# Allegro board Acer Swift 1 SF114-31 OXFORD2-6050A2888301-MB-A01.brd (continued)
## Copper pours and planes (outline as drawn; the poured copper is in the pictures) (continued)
P3V3AL on BOTTOM: 78.74,126.45 78.74,123.55 77.97,122.78 71.52,122.78 71.4,122.91 71.4,127.02 71.6,127.23 76.76,127.23 77.39,126.59 78.59,126.59
P3V3AL on BOTTOM: 65.5,126.82 65.5,128.22 64.13,128.22 64.13,126.82 64.03,126.72 63.32,126.72 62.51,127.53 62.51,128.57 63.32,129.39 68.81,129.39 69.36,128.83 73.78,128.83 75.69,126.92 75.13,126.36 72.03,126.36 71.02,127.38 67.18,127.38 66.52,126.72 65.61,126.72
P3V3S on TOP: 58.82,129.16 62.2,129.16 62.2,126.47 63.78,124.89 70.08,124.89 70.41,124.56 70.41,123.09 70.18,122.86 62.1,122.86 58.29,126.67 58.29,128.63
P3V3S on BOTTOM: 15.11,53.82 15.95,53.82 16.15,53.62 16.15,50.55 15.9,50.29 15.16,50.29 15.03,50.42 15.03,53.75
P3V3S on BOTTOM: 19.91,21.31 20.75,22.15 20.75,23.34 20.62,23.47 18.08,23.47 17.95,23.34 17.95,22.32 18.97,21.31
P3V3S on BOTTOM: 67.87,122.91 67.99,122.78 70.41,122.78 70.96,123.34 70.96,126.49 70.38,127.08 68.4,127.08 68.3,126.97 68.3,125.88 67.87,125.45
P3V3S on BOTTOM: 56.44,127.99 56.31,128.12 56.31,131.55 52.63,135.23 52.63,143.61 53.13,144.12 56.79,144.12 57.19,143.72 57.19,142.58 56.82,142.21 54.53,142.21 54.4,142.09 54.4,138.28 55.55,137.13 58.21,137.13 58.34,137.01 58.34,133.2 59.74,131.8 59.74,129.67 59.99,129.41 59.99,128.24 59.74,127.99
P3V3S on L4: 60.3,128.9 55.47,128.9 54.12,127.56 54.12,126.44 54.71,125.86 59.48,125.86 60.53,126.9 60.53,128.68
P3V3S on L5: 64.49,133.2 88.19,133.2 88.41,132.97 88.92,132.97 89.15,133.2 109.57,133.2 109.95,132.82 110.36,132.82 110.74,133.2 120.44,133.2 120.44,105.28 111.76,105.28 111.5,105.54 110.77,105.54 110.51,105.28 76.35,105.28 76.35,110.95 73.2,114.1 73.2,118.44 65.02,126.62 58.16,126.62 58.16,126.93 58.47,127.24 58.47,127.69 58.16,128 58.16,133.15 58.39,133.37 64.31,133.37
P3V3S_CR on TOP: 21,17.86 21,20.93 21.26,21.18 23.06,21.18 27.76,16.48 31.29,16.48 31.42,16.36 31.42,14.33 30.71,13.61 25.24,13.61
P3V3S_CR on BOTTOM: 20.11,18.87 20.11,21.1 20.7,21.69 24.94,21.69 25.07,21.56 25.07,20.42 24.81,20.17 22.4,20.17 22.27,20.04 20.57,20.04 20.42,19.88 20.42,18.89 20.39,18.87
P3V3S_LVDS1 on BOTTOM: 57.97,142.72 60.5,142.72 60.65,142.57 60.65,141.99 60.09,141.43 60.09,140.54 59.99,140.44 57.96,140.44 57.84,140.55 57.84,142.59
P3V3S_LVDS2 on BOTTOM: 60.75,139.17 60.63,139.29 60.63,140.23 60.37,140.49 60.37,141.17 60.91,141.71 60.91,142.62 61.01,142.72 61.77,142.72 61.9,142.85 61.9,143.81 65.66,147.57 65.66,150.01 66.24,150.6 66.24,152.27 67.36,153.39 68.02,153.39 68.15,153.26 68.15,151.1 67.28,150.24 67.28,147.75 63.34,143.81 63.34,140.72 61.79,139.17
P5V0A on TOP (solid shape): 36.12,123.88 36.12,121.97 32.81,118.67 32.05,118.67 31.85,118.87 31.85,121.06 34.92,124.13 35.86,124.13
P5V0A on TOP (solid shape): 38.48,139.34 38.48,138.61 38.05,138.18 37,138.18 35.61,136.78 34.59,136.78 34.59,137.92 36.42,139.75 38.07,139.75
P5V0A on L3 (solid shape): 39.04,139.17 39.04,138.25 38.68,137.9 36.85,137.9 36.17,138.58 36.17,139.29 36.62,139.75 38.45,139.75
P5V0A on L3 (solid shape): 73.3,136.96 73.3,133.43 84.86,121.87 85.65,121.87 85.95,121.56 85.95,121.21 84.99,120.24 84.15,120.24 71.73,132.66 71.73,136.32 69.95,138.1 68.53,138.1 68.53,139.62 70.63,139.62
P5V0A on TOP: 96.77,126.42 93.11,126.42 91.89,125.2 88.34,125.2 84.43,121.28 84.43,120.5 84.68,120.24 86.1,120.24 89.07,123.21 96.14,123.21 97.08,124.15 97.08,126.11
P5V0A on BOTTOM: 105.2,101.96 105.2,107.87 105.53,108.2 107.67,108.2 108.35,107.52 108.35,101.68 107.87,101.19 107.11,101.19 106.47,101.83 105.33,101.83
P5V0A on BOTTOM: 32.66,117.98 33.6,118.92 33.6,120.29 32.61,121.28 24.69,121.28 23.26,119.86 21.38,119.86 21,119.48 21,118.19 21.21,117.98
P5V0A on BOTTOM: 94.99,109.12 94.99,110.41 95.55,110.97 95.55,112.22 95.42,112.34 94.03,112.34 93.65,111.96 93.65,109.17 93.77,109.04 94.92,109.04
P5V0A on BOTTOM: 104.09,144.83 104.09,144.02 103.93,143.87 101.55,143.87 101.34,144.07 101.34,144.91 101.47,145.03 103.88,145.03
P5V0A on BOTTOM: 96.59,123.67 95.2,123.67 94.66,124.21 92.01,124.21 91.94,124.18 91.26,124.87 91.26,125.7 91.34,125.78 92.43,125.78 92.58,125.93 92.58,126.52 92.91,126.85 93.65,126.85 94.15,127.36 94.79,127.36 95.3,126.85 96.69,126.85 97.08,126.47 97.08,124.15
P5V0A on L4: 102.69,122.15 98.35,122.15 97.08,123.42 97.08,126.47 96.95,126.59 93.01,126.59 92.5,126.09 92.5,110.51 96.62,106.4 105.8,106.4 106.06,106.66 106.06,118.78
P5V0A_USB1 on BOTTOM: 20.39,116.74 18.89,116.74 18.67,116.51 16.86,116.51 16.51,116.15 15.87,116.15 15.26,116.76 15.26,118.19 16.1,119.02 20.65,119.02 20.8,118.87 20.8,117.86 20.93,117.73 22.32,117.73 22.45,117.6 22.45,115.19 22.32,115.06 20.93,115.06 20.8,115.19 20.8,116.33
P5V0A_USB2 on BOTTOM: 103.45,84.07 103.45,89.94 101.06,92.33 101.06,94.87 101.19,95 107.06,95 110.18,98.12 113.46,98.12 113.61,98.27 113.61,100.28 113.59,100.28 113.46,100.41 112.04,100.41 111.88,100.56 111.88,101.14 112.19,101.45 112.8,101.45 113.05,101.7 114.78,101.7 115.08,101.4 115.08,100.35 115.49,99.95 115.49,96.85 115.01,96.37 110.89,96.37 108.91,94.39 108.91,87.81 106.17,87.81 106.02,87.65 106.02,84.4 105.69,84.07
P5V0A_USB2_DB on TOP: 31.83,151.94 31.98,151.79 31.98,151.34 30.96,150.31 30.96,149.46 30.88,149.39 29.83,149.39 29.23,149.99 27.24,149.99 27.17,150.06 27.17,151.23 27.65,151.71 28.05,151.71 28.15,151.81 28.15,153.03 28.2,153.08 28.81,153.08 28.87,153.02 28.87,152.04 28.86,152.02 28.89,152.02 29.18,151.73 30.44,151.73 30.66,151.94
P5V0A_USB2_DB on BOTTOM: 48.9,160.09 48.9,157.87 48.78,157.75 47.45,157.75 47.21,157.98 47.21,159.96 47.34,160.09
P5V0A_USB2_DB on L3, L4: 18.06,148.65 17.46,149.25 17.46,152.2 17.58,152.32 21.15,152.32 21.29,152.3 21.42,152.23 22.04,152.16 22.46,152.63 23.91,152.63 23.91,152.62 38.84,152.62 45.33,159.11 49.15,159.11 49.51,158.75 49.51,155.07 43.78,149.34 22.59,149.34 21.9,148.65
P5V0A_USB_PW1 on BOTTOM: 105.53,98.83 105.53,100.89 108.1,100.89 108.56,101.35 110.74,101.35 111.02,101.07 111.02,100.1 110.54,99.62 109.22,99.62 108.2,98.6 105.76,98.6
P5V0S on BOTTOM: 19.35,50.14 16,50.14 15.85,49.99 15.85,49.33 16.81,48.36 19.35,48.36 19.48,48.49 19.48,50.01
P5V0S on BOTTOM: 87.5,122.2 87.5,123.6 88.11,124.21 88.11,124.99 87.91,125.2 84.76,125.2 84.17,125.78 83.16,125.78 82.57,125.2 82.57,122.15 87.45,122.15
P5V0S on BOTTOM: 8.1,58.04 8.1,59.56 14.2,59.56 14.32,59.44 14.32,58.93 13.43,58.04
P5V0S on L4: 39.21,132.33 66.11,132.33 71.04,127.41 84.19,127.41 84.86,126.74 84.86,124.26 83.84,123.24 70.71,123.24 64.79,129.16 45.69,129.16 20.39,103.86 20.39,57.66 20.37,57.63 17.52,57.63 16.94,57.05 15.97,57.05 15.39,57.63 12.37,57.63 12.24,57.76 12.24,59.79 12.37,59.92 17.45,59.92 18.12,60.59 18.12,109.49 37.92,129.29 37.92,131.04
P5V0S_AUDIO_AVDD on BOTTOM: 12.37,57.78 13.43,56.72 13.43,55.88 13.18,55.63 7.21,55.63 7.08,55.75 7.08,57.78
P5V0S_PVDD on BOTTOM: 14.78,50.11 12.06,50.11 11.68,49.73 11.1,49.73 10.41,49.05 10.41,48.44 10.87,47.98 11.4,47.98 11.88,48.46 14.45,48.46 14.96,48.97 14.96,49.94
PVBAT on TOP: 75.97,11.58 66.85,20.7 58.26,20.7 55.72,23.24 54.58,23.24 51.71,20.37 46.91,20.37 45.56,21.72 45.56,30.38 46.81,31.62 71.8,31.62 73.58,33.4 84.96,33.4 89.56,28.8 104.37,28.8 106.88,31.32 106.88,38.43 105.33,39.98 105.33,40.41 104.97,40.77 104.97,42.58 104.06,43.48 104.06,45.54 103.53,46.08 103.53,49.83 104.97,51.27 104.97,97.57 107.73,100.33 107.73,116.93 102.92,121.74 99.82,121.74 98.24,123.32 98.24,125.65 96.28,127.62 95.04,127.62 92.94,129.72 88.67,129.72 87.09,128.14 82.42,128.14 81.99,127.71 81.73,127.71 81.3,128.14 75.23,128.14 68.22,135.15 67.76,135.15 67.43,135.48 67.43,137.44 67.64,137.64 72.49,137.64 76.78,133.35 82.9,133.35 84.78,135.23 96.08,135.23 99.88,131.43 107.86,131.43 115.49,123.8 115.49,90.73 124.69,90.73 124.69,16.53 109.62,16.53 109.62,12.01 109.19,11.58
PVBAT on BOTTOM: 102.1,78.21 102.1,79.25 102.38,79.53 105.53,79.53 105.89,79.17 105.89,76.86 105.64,76.61 101.7,76.61 101.52,76.78 101.52,77.62
PVBAT on BOTTOM: 83.82,131.42 83.23,132 83.23,133.55 84.27,134.59 84.27,138.53 84.1,138.71 84.1,141.83 84.27,142.01 84.27,145.72 83.84,146.15 83.33,146.15 82.83,146.66 82.83,148.21 82.09,148.95 82.09,150.44 81.38,151.15 81.38,153.24 81.56,153.42 82.22,153.42 82.5,153.14 82.5,151.99 83.84,150.65 83.84,147.73 85.8,145.77 87.04,145.77 87.27,145.54 87.27,144.47 86.61,143.81 86.61,131.65 86.38,131.42
PVBAT on BOTTOM: 85.32,32.38 85.11,32.59 78.89,32.59 78.36,33.12 78.36,36.88 79.14,37.67 90.73,37.67 91.13,37.26 91.13,32.82 90.7,32.38
PVBAT on BOTTOM: 52.12,21.89 52.12,19.48 51.43,18.8 47.65,18.8 47.42,19.02 47.42,19.76 48.01,20.35 48.01,21.77 48.41,22.17 51.84,22.17
PVBAT on BOTTOM: 72.29,26.42 75.41,26.42 75.79,26.03 75.79,25.09 75.41,24.71 72.29,24.71 72.11,24.89 72.11,26.24
PVBAT on BOTTOM: 70.02,135.76 70.02,143.23 66.49,143.23 66.29,143.02 66.29,135.25 69.52,135.25
PVBAT_CPU on BOTTOM: 94.21,81.03 102.18,81.03 102.41,80.8 102.41,80.06 101.8,79.45 101.8,78.76 101.11,78.08 101.11,76.96 100.89,76.73 99.54,76.73 98.27,78 94.48,78 94.05,78.43 94.05,80.87
PVBAT_VGG on BOTTOM: 84.91,43.36 89.23,43.36 89.56,43.69 93.06,43.69 93.27,43.48 93.27,39.34 92.53,38.61 87.7,38.61 85.7,40.61 84.93,40.61 84.53,41.02 84.53,42.98
PVADPTR on TOP: 19.61,114.63 19.61,105.71 19.91,105.41 21.41,105.41 22.45,106.45 22.45,111.12 31.21,119.89 31.21,133.63 30.68,134.16 26.95,134.16 26.59,133.81 26.59,121.61
PVADPTR on TOP: 32.1,15.72 32.1,19.61 32.33,19.84 53.29,19.84 54.1,19.02 54.1,15.62 53.92,15.44 32.38,15.44
PVADPTR on BOTTOM: 20.24,41.5 20.24,55.9 18.74,57.4 18.74,66.62 16.86,68.5 16.86,106.07 17.9,107.11 21.28,107.11 21.51,106.88 21.51,105.56 19.35,103.4 19.35,70.66 21.46,68.55 21.46,58.34 23.01,56.79 23.01,38.02 14.22,29.23 14.22,13.84 17.24,10.82 21.38,10.82 27.85,17.29 27.85,19.21 29.06,20.42 34.08,20.42 34.95,19.56 34.95,18.31 34.69,18.06 32.56,18.06 32.33,17.83 32.33,13.74 31.01,12.41 31.01,5.98 10.06,5.98 10.06,31.32
PVADPTR on BOTTOM: 28.04,134.21 24.91,134.21 24.43,133.73 24.43,132.46 26.34,130.56 28.14,130.56 28.32,130.73 28.32,133.93
PVCORE on BOTTOM (solid shape): 99.23,101.4 99.23,98.55 98.98,98.3 94.15,98.3 93.24,97.38 93.24,85.65 92.76,85.17 90.19,85.17 90.09,85.27 90.09,85.85 91.28,85.85 91.28,86.38 90.09,86.38 90.09,86.6 88.3,88.39 88.3,94.42 86.03,96.7 86.03,99.26 85.09,100.2 85.09,101.55 85.21,101.68 98.96,101.68
PVCORE on TOP: 65.73,82.7 65.86,82.57 65.86,82.19 65.73,82.06 65.48,82.06 65.35,81.94 65.35,80.64 62.96,80.64 62.96,81.84 63.04,81.91 63.43,81.91 63.43,81.47 63.62,81.28 64.26,81.28 64.45,81.47 64.45,81.91 64.51,81.91 65.3,82.7
PVCORE on TOP: 62.94,84.73 63.7,85.49 63.7,86.38 63.83,86.51 64.22,86.51 64.22,85.72 64.27,85.67 64.27,85.21 64.3,85.19 64.3,84.3 64.45,84.15 64.45,83.7 64.33,83.59 63.06,83.59 62.94,83.72
PVCORE on BOTTOM: 63.15,80.67 64.97,80.67 65.1,80.79 65.1,81.56 65.86,82.32 65.86,82.57 65.48,82.95 65.13,82.95 64.9,82.72 64.73,82.72 64.5,82.95 63.45,82.95 63.45,82.19 63,81.75 63,81.56 63.15,81.4 63.15,81.12 63,80.97 63,80.82
PVCORE on BOTTOM: 63.19,83.72 64.21,83.72 64.59,84.1 64.59,84.86 65.35,85.62 65.35,86 64.59,86.76 63.57,86.76 63.45,86.64 63.45,85.24 63.06,84.86 63.06,83.84
PVCORE on L4: 78.79,82.04 69.21,82.04 68.91,81.74 68.91,80.54 68.63,80.26 67.26,80.26 66.95,79.96 63.8,79.96 63.07,80.7 63.07,82.04 63.65,82.63 63.65,83.41 63.17,83.9 63.17,85.84 63.94,86.61 64.81,87.48 64.81,89.43 65.35,89.97 69.16,89.97 69.16,87.68 70.23,86.61 71.73,86.61 73.89,88.77 73.89,93.62 74.29,94.03 74.29,99.19 77.69,102.59 88.9,102.59 91.23,100.25 91.23,89.99 89.05,87.81 84.55,87.81
PVCORE on L5: 65.81,80.73 65.34,80.26 60.49,80.26 60.49,84.51 61.76,85.78 61.76,87.29 62.51,88.04 62.51,92.13 64.03,93.65 64.03,93.68 64.01,93.7 64.01,94.37 64.13,94.5 64.13,98.25 65.81,99.92 65.81,102.41 68.42,105.03 91.23,105.03 91.23,96.04 91.08,95.88 73.1,95.88 67.54,90.32 67.54,89.18 67.11,88.76 67.11,84.43 65.1,84.43 65.1,83.21 65.81,82.5
PVGG on TOP: 63.67,76.33 64.11,75.89 65.27,75.89 65.55,76.17 65.55,78.43 65.07,78.92 64.69,78.92 64.52,78.74 64.52,78.38 64.31,78.17 63.8,78.17 63.67,78.05
PVGG on BOTTOM: 83,51.49 84.2,50.29 90.75,50.29 91.44,50.98 91.44,52.58 89.53,54.48 89.53,55.68 89.25,55.96 84.35,55.96 83,54.61
PVGG on BOTTOM: 63.86,76.83 63.86,76.19 64.33,75.71 65.99,75.71 66.24,75.97 66.24,77.49 65.31,78.42 65.31,79.05 64.46,79.91 62.81,79.91 62.68,79.78 62.68,79.65 63.57,78.76 63.57,78.51 63.45,78.38 63.45,77.25
PVGG on BOTTOM: 90.04,64.11 87.68,64.11 87.6,64.03 87.6,63.19 87.63,63.17 90.04,63.17 90.09,63.22 90.09,64.06
PVGG on L4: 64.41,78.87 65.88,78.87 66.24,78.51 66.24,76.45 70.08,72.62 70.08,69.6 70.38,69.29 73.58,69.29 74.34,68.53 84.05,68.53 84.76,67.82 84.76,62.97 85.29,62.43 87.09,62.43 87.53,62.86 87.53,64.11 87.78,64.36 90.27,64.36 90.9,63.73 90.9,53.62 89.3,52.02 74.19,52.02 64.77,61.44 64.77,62.56 64.11,63.22 64.11,68.25 63.95,68.4 63.95,69.42 63.24,70.13 62.84,70.13 62.84,77.29 ; 1 cut-out
PVGG on L5: 68.02,74.68 69.52,73.18 69.52,70 70.23,69.29 73.58,69.29 74.34,68.53 84.05,68.53 84.76,67.82 84.76,62.97 85.29,62.43 89.96,62.43 89.96,52.68 87.22,49.94 84.76,49.94 83.13,48.31 70.46,48.31 69.14,49.63 69.14,57.07 64.77,61.44 64.77,62.56 64.11,63.22 64.11,68.25 63.95,68.4 63.95,69.42 63.24,70.13 62.51,70.13 62.07,70.56 62.07,76.48 61.72,76.83 61.72,78.94 62.78,80.01 65.73,80.01 68.02,77.72 ; 1 cut-out
PVPACK on BOTTOM: 82.7,29.69 86.48,29.69 86.76,29.97 86.76,31.98 86.89,32.11 89.48,32.11 89.89,31.7 89.89,28.96 88.21,27.28 88.21,23.52 87.96,23.27 85.19,23.27 84.73,23.72 84.73,26.69 84.45,26.97 82.62,26.97 82.47,27.13 82.47,29.46
SDIO_V3P3A_V1P8A on BOTTOM: 75.43,69.29 76.53,69.29 78.89,66.93 78.89,64.06 78.64,63.8 77.44,63.8 77.34,63.91 77.34,66.22 75.38,68.17 75.38,69.24
UNNAMED_5_BEADSINGLE_I57_INA on BOTTOM: 74.95,30.45 75.03,30.38 75.03,29.97 74.9,29.84 74.24,29.84 74.14,29.74 74.14,27.63 73.91,27.41 70.58,27.41 68.63,29.36 68.63,30.17 68.91,30.45
UNNAMED_5_BEADSINGLE_I76_INA on BOTTOM: 23.97,134.87 23.97,139.01 24.36,139.39 27.2,139.39 27.73,138.86 27.73,134.95 27.38,134.59 24.25,134.59
UNNAMED_5_POWERINDUCTOR_I49_2 on BOTTOM: 84.25,25.45 81.76,25.45 80.92,26.29 77.11,26.29 76.6,25.78 76.6,23.85 76.17,23.42 76.17,23.01 76.43,22.76 80.64,22.76 81.45,23.57 84.2,23.57 84.43,23.8 84.43,25.27
UNNAMED_6_CSC0805_I6_A on BOTTOM: 92.88,145.52 92.76,145.64 87.75,145.64 87.63,145.52 87.63,144.14 87.04,143.56 87.04,142.72 87.17,142.6 90.09,142.6 90.22,142.47 90.22,141.71 90.34,141.58 91.61,141.58 92.5,140.69 92.76,140.69 92.88,140.82
UNNAMED_6_CSC0805_I27_A on BOTTOM: 73.58,145.26 73.45,145.39 67.23,145.39 66.98,145.14 66.98,144.42 67.13,144.27 68.22,144.27 68.86,143.64 71.14,143.64 71.8,142.98 71.8,142.21 73.33,140.69 73.45,140.69 73.58,140.82
UNNAMED_9_IDUT4PIN_I34_2 on BOTTOM: 88.49,87.2 87.22,87.2 84.27,84.25 84.27,79.73 85.04,78.97 87.91,78.97 88.67,79.73 88.67,87.02
UNNAMED_11_IDUT4PIN_I27_2 on BOTTOM: 81.28,53.77 79.68,53.77 79.37,53.47 79.37,51.56 78.64,50.82 78.64,48.16 79.09,47.7 82.95,47.7 83.36,48.11 83.36,50.22 82.39,51.18 82.39,51.59 82.09,51.89 81.68,51.89 81.63,51.94 81.63,53.42
UNNAMED_13_CSC0603_I58_A on BOTTOM: 97.51,123.37 97.46,123.42 94.79,123.42 94.28,123.93 93.39,123.93 93.27,123.8 93.27,122.78 93.39,122.66 95.55,122.66 95.68,122.53 95.68,118.72 97.46,116.94 97.96,116.94 97.96,117.96 97.51,118.41
UNNAMED_13_CSC0603_I80_A on BOTTOM: 95.88,110.54 95.35,110.01 95.35,108.94 95.6,108.69 97.69,108.69 97.84,108.84 97.84,114.02 97.33,114.02 95.88,112.57
UNNAMED_15_APL3523A_I201_8 on BOTTOM: 90.04,125.65 90.04,122.22 89.96,122.15 88.06,122.15 87.83,122.38 87.83,123.19 88.41,123.77 88.41,125.07 89.13,125.78 89.91,125.78
UNNAMED_15_APL3523A_I201_13 on BOTTOM: 90.04,127.28 90.04,128.68 89.3,129.41 88.87,129.41 88.72,129.26 88.72,128.75 88.19,128.22 88.19,127.61 88.31,127.48 88.69,127.48 89,127.18 89.94,127.18
UNNAMED_15_APL3523A_I202_8 on BOTTOM: 66.42,126.26 66.42,125.75 66.16,125.5 65.61,125.5 65.5,125.4 65.5,124.48 65.81,124.18 65.81,123.82 65.99,123.65 66.24,123.65 66.77,124.18 67.23,124.18 67.43,124.38 67.43,125.75 68.02,126.34 68.02,126.97 67.92,127.08 67.23,127.08
UNNAMED_15_APL3523A_I202_13 on BOTTOM: 62.07,125.98 61.52,125.42 61.52,124.31 61.9,123.92 63.49,123.92 64.13,124.56 64.13,125.5 63.47,125.5 63.29,125.68 63.29,126.34 62.58,127.05 62.13,127.05 62.07,127
UNNAMED_24_CSC0402_I46_A on TOP: 99.72,37.39 102.38,37.39 103.02,36.75 103.02,34.57 102.61,34.16 100.81,34.16 100.17,33.53 98.68,33.53 97.2,35 97.2,42.42 97.58,42.8 98.93,42.8 99.44,42.29 99.44,37.67
UNNAMED_24_CSC0402_I46_A on BOTTOM: 100.81,36.37 102.69,36.37 103.07,35.99 103.07,33.98 102.59,33.5 100.78,33.5 100.33,33.96 100.33,35.89
UNNAMED_51_ALC233VB2CGT_I110_AV on BOTTOM (solid shape): 13.1,43.61 13.1,43.18 12.32,42.39 12.32,42.11 11.76,41.55 11.76,40.97 11.63,40.84 11.3,40.84 11.05,41.1 11.05,43.79 11.15,43.89 12.82,43.89
VRA3V3A_LDO on BOTTOM: 76.73,139.29 76.98,139.04 77.47,139.04 77.64,139.22 77.64,139.93 77.24,140.33 77.24,141.1 77.77,141.63 77.77,143.03 77.62,143.18 76.91,143.18 76.73,143
VRACHG_ACDRV1 on TOP: 53.31,20.57 53.31,20.19 54.43,19.07 54.43,18.34 54.53,18.24 55.47,18.24 55.8,18.57 55.8,20.17 55.27,20.7 53.44,20.7
VRACHG_CMSRC1 on TOP: 56.56,20.88 57.05,20.88 57.55,20.37 57.55,17.04 57.48,16.97 56.44,16.97 55.34,15.87 54.61,15.87 54.43,16.05 54.43,17.73 54.53,17.83 55.5,17.83 56.16,18.49 56.16,20.47
VRACHG_MP1 on TOP: 62.91,19.3 61.11,19.3 60.63,19.79 58.09,19.79 57.88,19.58 57.88,15.67 58.11,15.44 62.99,15.44 63.4,15.85 63.4,18.82
VRACHG_PH on BOTTOM (solid shape): 82.06,31.9 82.06,29.67 80.67,28.27 77.64,28.27 75.18,30.73 72.34,30.73 72.26,30.81 72.26,31.67 72.36,31.77 75.79,31.77 76.17,32.16 81.81,32.16
VRACHG_REGN on BOTTOM: 65.61,25.58 68.55,25.58 68.7,25.42 68.7,24.51 68.35,24.15 66.65,24.15 66.19,23.7 65.78,23.7 65.48,24 65.48,25.45
VRP1V05A on BOTTOM: 88.31,107.42 88.31,104.83 88.62,104.52 98.7,104.52 99.49,103.73 99.49,102.97 99.62,102.84 102.66,102.84 103.17,102.34 103.93,102.34 104.06,102.46 104.06,104.37 103.93,104.5 101.55,104.5 101.19,104.85 101.19,106.91 100.4,107.7 88.59,107.7
VRP1V05A_PH on BOTTOM (solid shape): 97.08,114.15 95.55,112.62 93.95,112.62 92.2,110.87 88.54,110.87 88.49,110.92 88.49,113.18 88.72,113.41 90.78,113.41 91.84,114.48 93.01,114.48 93.37,114.83 97.08,114.83
VRP1V5S on BOTTOM: 103.17,115.67 103.17,116.43 103.3,116.56 104.8,116.56 105.23,116.13 105.23,115.59 104.92,115.29 104.92,114.81 104.87,114.76 104.34,114.76 104.24,114.86 104.24,115.37 104.06,115.54 103.3,115.54
VRP1V8A on BOTTOM (solid shape): 105.47,117.96 105.47,117.8 105.34,117.67 104.94,117.67 104.31,117.04 102.03,117.04 101.24,116.26 100.1,116.26 100.02,116.33 100.02,116.89 99.74,117.17 99.74,117.73 100.23,118.21 105.22,118.21
VRP1V8A on TOP: 97.15,121.69 90.32,121.69 89.46,120.83 89.46,117.7 90.4,116.76 104.29,116.76 105.33,117.8 105.33,118.24 104.8,118.77 100.07,118.77
VRP1V8A on BOTTOM: 90.6,122.4 90.09,121.89 89.33,121.89 89.2,121.77 89.2,113.89 89.4,113.69 90.52,113.69 90.85,114.02 90.85,118.85 91.11,119.1 95.3,119.1 95.42,119.23 95.42,122.28 95.3,122.4
VRP1V8A_PH on BOTTOM (solid shape): 97.08,116.94 97.08,116.36 96.97,116.26 95.83,116.26 95.63,116.46 91.23,116.46 91.11,116.59 91.11,118.57 91.34,118.8 95.22,118.8
VRP1V15 on BOTTOM: 103.55,121.77 103.55,121.39 102.92,120.75 102.92,119.74 102.79,119.61 101.9,119.61 101.77,119.74 101.77,122.28 101.9,122.4 102.36,122.4 102.89,121.87 103.45,121.87
VRP1V24A on BOTTOM: 99.11,121.26 101.39,121.26 101.52,121.39 101.52,122.28 101.39,122.4 100,122.4 99.87,122.53 99.87,124.05 100,124.18 100.76,124.18 100.89,124.31 100.89,124.69 100.76,124.82 100.25,124.82 99.74,125.32 99.11,125.32 98.98,125.2 98.98,121.39
VRP3V3A on BOTTOM: 78.31,126.97 77.72,126.97 77.14,127.56 75.87,127.56 74.32,129.11 70.63,129.11 70.28,129.46 70.28,133.07 70.41,133.2 78.38,133.2 79.52,132.05 79.52,128.19
VRP3V3A_PH on BOTTOM: 73.2,140.31 73.2,139.04 73.07,138.91 72.06,138.91 71.93,138.79 71.93,138.02 71.8,137.9 70.41,137.9 70.28,137.77 70.28,135.36 70.41,135.23 74.6,135.23 75.41,136.04 75.41,138.28 74.72,138.96 74.72,140.31 74.6,140.44 73.33,140.44
VRP5V0A on BOTTOM: 89.84,132.46 89.84,129.92 90.4,129.36 93.67,129.36 93.9,129.13 93.9,127.74 94.03,127.61 95.04,127.61 95.55,127.1 96.44,127.1 98.35,129.01 100,129.01 100.29,129.3 100.29,132.74 99.86,133.17 90.55,133.17
VRP5V0A_PH on BOTTOM: 94.03,140.31 94.03,139.17 94.28,138.91 94.28,135.36 94.15,135.23 90.6,135.23 90.47,135.36 90.47,137.9 91.36,138.79 92.38,138.79 92.5,138.91 92.5,140.31 92.63,140.44 93.9,140.44
VRPCHG_LG on BOTTOM (solid shape): 75.89,32.89 75.89,32.31 75.66,32.08 74.47,32.08 74.42,32.13 74.42,32.89 74.57,33.04 75.74,33.04
VRPVCORE_PH1 on BOTTOM: 98.37,83.79 93.72,83.79 93.21,84.3 91.18,84.3 90.07,83.18 90.07,79.93 91.03,78.97 92.99,78.97 93.67,79.65 93.67,80.87 94.21,81.41 98.29,81.41 98.4,81.51 98.4,83.77
VRPVDDQ on BOTTOM: 38.94,35.58 39.82,35.58 40.18,35.23 41.55,35.23 41.91,35.58 50.49,35.58 51.58,34.49 51.58,31.77 50.62,30.81 46.89,30.81 45.39,32.31 38.5,32.31 38.33,32.49 38.33,34.98
VRPVDDQ_PH on BOTTOM (solid shape): 45.39,23.95 45.39,23.37 45.18,23.16 44.8,23.16 44.7,23.27 44.7,23.72 43.89,24.54 43.38,24.54 43.38,24.94 43.41,24.97 44.37,24.97
VRPVDDQ_PH on BOTTOM: 50.47,24.69 50.44,24.71 50.44,25.55 50.19,25.81 46.78,25.81 45.77,26.82 40.69,26.82 40.69,28.07 43.81,28.07 43.91,28.17 44.8,28.17 45.95,29.31 50.77,29.31 51.3,28.78 51.3,24.71 51.28,24.69
VRPVDDQ_VIN on BOTTOM: 43.58,26.47 43.68,26.57 45.62,26.57 47.09,25.09 47.09,19.02 46.83,18.77 45.46,18.77 45.01,19.23 45.01,20.62 45.74,21.36 45.74,24.28 44.73,25.3 42.08,25.3 41.96,25.42 41.96,26.36 42.06,26.47
VRPVGG_PH1 on BOTTOM: 89.2,46.02 79.5,46.02 78.91,45.44 78.91,42.67 79.3,42.29 83.05,42.29 84.4,43.64 89.13,43.64 89.33,43.84 89.33,45.9
VRPVTT on BOTTOM (solid shape): 40.97,23.24 41.83,23.24 41.93,23.14 41.93,22.66 41.91,22.63 41.91,22.05 42.26,21.69 43.08,21.69 43.25,21.51 43.25,20.57 43.08,20.4 42.49,20.4 42.03,20.85 41.2,20.85 40.94,21.11 40.94,21.69 40.15,22.48 40.15,23.42 40.31,23.57 40.64,23.57
VRPVTT_REF on BOTTOM (solid shape): 40.31,25.32 40.31,24.92 39.62,24.23 38.83,24.23 37.54,22.94 32.53,22.94 32.2,23.27 32.2,24.84 32.38,25.02 32.89,25.02 33.45,24.46 37.97,24.46 38.89,25.37 40.26,25.37

Small or netless copper shapes (teardrops, artwork), in the pictures only: 975 on TOP, 1403 on BOTTOM, 973 on L3, 1052 on L4

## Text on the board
Ref Des/Silkscreen Bottom: 6050A2901401 | -PWRBUTTON-A01
User.Comments: CR_UNNAMED_1
Ref Des/Silkscreen Top: 6050A2888201-USB-A01 | N15V2 | OXFORD2-6050A2888301-MB-A01
User.14: short_0402_15 | 22pF_50V_2_DY | AMC_AZC099_04S_R7G_SOT23_6P | 0.22uF_6.3V_2 | SFI_SFI0402ML120C_LF_SMD_2P_DY | 0.1uF_10V_2_DY | 0.1uF_16V_2_DY | 0.047uF_16V_2_DY | SFI_SFI0402ML120C_LF_SMD_2P | SFI0402_050E3R0PP_LF | SFI_SFI0402_050E050PP_LF_SMD_2P | POWERPAD1x1m | CSC0402_DY | 0.1uF_16V_2 | 0.1uF_10V_2 | 18pF_50V_2 | MCF12102G900-T | 80.6_1%_2 | 0.2pF_50V_2 | 1000PF_50V_2 | 470pF_50V_2 | 1uF_6.3V_2 | 2.2uF_6.3V_2 | short_0402_5 | DIODE-BAT54-TAP-PHP | 10uF_6.3V_3_DY | 10K_5%_2_DY | 10K_1%_2_DY | 100pF_50V_2 | 2.49K_1%_2 | 0.1uF_25V_2 | 12pF_50V_2 | 20K_1%_2_DY | 1K_5%_2_DY | 22pF_50V_2 | FBM_11_160808_121T | 180pF_50V_2 | RSC_0402_DY | 10_5%_2_DY | 10uF_6.3V_3 | short_0603_25 | 100_5%_2 | 0_5%_2_DY | 4.7K_1%_2 | 243_1%_2 | 150_5%_2 | 470_5%_2 | 0.1uF_25V_3 | 182_1%_2 | 8.2K_5%_2 | 100_1%_2 | 4.7uF_6.3V_3 | 10K_5%_2 | 402_1%_2 | 4.7K_5%_2 | 45.3_1%_2 | 200_1%_2 | 301_1%_2 | 49.9_1%_2 | 1uF_10V_2 | 20K_5%_2 | 100K_5%_2 | POWERPAD2x2M_DY | 3.3K_5%_2 | 1.8K_5%_2 | 47K_5%_2 | RU1C001UNTCL | 120_1%_2 | 2.2K_5%_2 | 200K_5%_2 | 619_1%_2 | 75_5%_2 | 150_1%_2 | L2N7002WT1G | 0_5%_2 | 22uF_6.3V_5 | 2.2_5%_3 | 1K_5%_2 | 0_5%_3_DY | REA_ALC233_VB2_CGT_MQFN_48P | RQ3E100BNFU7TB | RQ3E070BNFU7TB | PASSWORD_0805 | 10_5%_2 | TP24 | SCREW260_1000_600_1P | SCREW260_550_1P | SCREW300_1000_700_1P | FIX_MASK | SCREW260_700_600_1P | STANDOFF_3.1_5.5 | 0_5%_3 | SCREW260_1000_800_1P | SCREW260_700_1P | SCREW260_800_700_1P | 1A_32V | 0.02_1%_6 | PM513BA | ACES_50503_0104N_001_10P | WINB_NPCE985LB1DX_LQFP_128P | TAITWUN_PSDATG_11GLBS1NN4H1_11P
User.15: 470pF_50V_2_DY | LITEON_L30ESDXVC3_2_DSOT23_3P_DY | AMC_AZC099_04S_R7G_SOT23_6P | 6.8PF_50V_2_DY | TSB_TC7SZ07FU_SSOP_5P | LITEON_L30ESDXVC3_2_DSOT23_3P | EVL_19_223_ S2T1D _C30_2T_4P | MH251EST_MH251EST_TSOT23_3P | short_0402_15 | SFI_SFI0402ML120C_LF_SMD_2P_DY | 0.1uF_16V_2_DY | TI_TCA9406DCUR_VSSOP_8P_DY | TI_TCA9406DCUR_VSSOP_8P | SFI_SFI0402_050E050PP_LF_SMD_2P | AMC_AZ2015_01H_SOD523_2P_DY | AMAZING_AZ1045_04F_R7G_10P | 0.022uF_16V_2_DY | 6.04K_1%_1/16W_2 | 0.047uF_16V_2 | 1000PF_50V_2_DY | TI_TS3USB221ARSER_QFN_10P | SFI_SFI0603_240E2R5PP_LF_2P_DY | SFI_SFI0402ML120C_LF_SMD_2P | CSC0402_DY | POWERPAD1x1m | 0.1uF_16V_2 | 100pF_50V_2 | MCF12102G900-T | 1uF_6.3V_2 | 10pF_50V_2 | 1000PF_50V_2 | short_0402_5 | 0.01uF_50V_2 | 680pF_50V_2 | ANPEC_APL3523A_TDFN_14P | 18.7K_1%_2 | 53.6K_1%_2 | GMT_AT9667_MSOP8_8P | 100K_1%_NTC | 0.1uF_25V_2 | 2200pF_50V_2 | 15pF_50V_2 | 0.1uF_25V_3_DY | 4.02K_1%_2 | 470pF_50V_2 | 46.4K_1%_2 | 1.2pF_50V_2 | RSC_0402_DY | 4700pF_50V_2 | 8.25K_1%_2 | 0.22uF_16V_2 | 10K_5%_2_DY | DIODE-BAT54-TAP-PHP | L2N7002WT1G_DY | 2.2uF_6.3V_2 | 4.7uF_6.3V_3_DY | 10uF_6.3V_3_DY | GMT_G5250Q1T73U_SOT23_3P | GMT_G524B1T11U_SOT23_5P | 180pF_50V_2 | KC_FBMA_11_321611_121A60T | 56.2K_1%_2 | 20.5K_1%_2 | 220pF_50V_2 | 1K_5%_2_DY | 150_5%_2_DY | 4.7K_5%_2_DY | 32.4K_1%_2 | 12pF_50V_2 | 330pF_50V_2 | 36.5K_1%_2 | 34.8K_1%_2 | 48.7K_1%_2 | 22.1K_1%_2 | 100K_5%_2_DY | RU1C001UNTCL_DY | 2.2K_5%_2_DY | 0_5%_2_DY | 2.2K_5%_2 | 10uF_6.3V_3 | short_0603_25 | 4.7uF_6.3V_3 | RU1C001UNTCL | REA_RTS5170_GRT_QFN_24P | WCM_2012SHS_850T | L2N7002WT1G | 10K_5%_2 | 243_1%_2 | L2N7002DW1T1G | BAT54_30V_0.2A_DY | 10K_1%_2 | 511K_1%_2 | POWERPAD_2_0610 | 10UF_25V_5_DY | 22UF_6.3V_3 | 470K_5%_2 | 200_5%_2 | 47K_5%_2 | 0.1uF_25V_3 | 100_5%_2 | BAT54C_30V_0.2A | 1uF_10V_2 | 100K_5%_2 | 20K_5%_2 | 4.7K_5%_2 | MXIC_MX25U6435FM2I_10G_SOP_8P | 301_1%_2 | 200_1%_2 | RSC_0603_DY | 4.7uF_25V_3 | 10M_5%_2 | 33pF_50V | 3.3K_1%_2 | 49.9_1%_2 | 100K_1%_2 | 2.2uF_6.3V_3 | RICHTEK_RT5041AGQW_WQFN_28P | 100_1%_2 | 220K_5%_2 | 4.7uF_10V_3 | 6.2K_1%_2 | 47uF_6.3V_5_DY | 8.2K_1%_2 | 22uF_6.3V_5_DY | 14K_1%_2 | 4.3K_5%_2 | 3.32K_1% | TI_BQ24725ARGRR_QFN_20P | 91K_5%_2 | 110K_5%_2 | 2.7K_5%_2 | MPS_NB670GQ_QFN_16P | 620K_5%_2 | 150K_5%_2 | 5.1_5%_2 | short_0603_10 | 200K_5%_2 | 75K_1%_2 | MPS_NB671LGQ_QFN_16P | 0_5%_2 | 1K_5%_2 | 10UF_25V_5 | FDC638APZ_DY | LMBT3904LT1G | 10_5%_2 | 33_5%_2 | 0_5%_3_DY | 4.7uF_25V_5 | 113_1%_3 | 22_5%_2 | LCN_AWM10_0429980_0004_4P | 4.7_5%_3 | RQ3E100BNFU7TB | 2.2_5%_3 | 22uF_6.3V_5 | 1K_1%_2 | 10_1%_2 | ON_NCP81201_QFN_28P | FAIRCHILD_FDMS3669S | TC7SZ08FU | DIP_TMG_533_Q_T_R_6P | GMT_G5388K11U_QFN_32P | 4.7K_5%_3 | 3M_5%_2 | 1M_5%_2 | 1uF_25V_3 | CSC0805_DY | 10uF_6.3V_5 | XTAL_4PIN_19.2MHZ | NUVOTON_NPCT650AAAWX_TSSOP_28P_DY | 100uF_6.3V_DY | HR_A1255WR_S_05PNLNT1TS1R_5P | SCREW260_700_600_1P | FAIR_FDMS3664S_8P | TP24 | SCREW260_550_1P | FIX_MASK | SAMSUNG_K4B4G1646Q_HYK0_FBGA_96P | ACER_50505_0044N_002_4P | SCREW260_800_700_1P | STANDOFF_3.1_5.5 | 0.002_1%_6 | 0_5%_3 | SINGA_2SJ3095_078111F_6P | 10_5%_5 | NRS5020T1R0N | SCREW260_700_1P | SCREW300_1000_700_1P | PM513BA | 0_5%_5 | AON7934 | SCREW260_1000_800_1P | SCREW260_1000_600_1P | 0.02_1%_6 | 32.768KHZ_12.5PF | TOSHIBA_THGBMBG8D4KBAIR_FBGA_153P | LOTES_APCI0062-P001A_NGFF_E_KEY_75P | PCMB061H-R33MS | PCMB061H-1R0MS | BAV99 | PCMB061H-2R2MS | PCMB061H_4R7MS | PCMB061H_R47MS | ACES_50503_0104N_001_10P | ACES_50503_0084N_001_8P | SUYIN_020173GR004M59GZL_4P | CONCRAFT_099A4AC19HBLBNF_19P | ALLTOP_C107MK_9093D_L_9P | ACES_50203_03001_001_30P | 15uF_25V_DY | 220uF_2V_10% | ACES_50299_00901_001_9P | 470uF_2V | ACES_50503_0244N_001_24P | CPU_540276_BGA_1170P | 100uF_6.3V
User.34: B | A | 1 | 2 | 3
User.45: FIGURE | SIZE | 10.0 | 16.0 | 20.0 | 28.0 | 36.0 | 102.0 | 118.0 | 122.0 | 25.0 | 43.0 | 45.0 | 49.0 | 63.0 | 68.9 | 79.0 | 87.0 | 158.0 | 57.0x26.0 | 71.0x31.0 | 79.0x31.0 | 79.0x35.0 | 85.0x43.0 | 91.0x35.0 | 93.0x31.0 | 134.0x24.0 | 98.0x87.0 | DRILL CHART: TOP to BOTTOM | ALL UNITS ARE IN MILS | PLATED | NON-PLATED | QTY | 3107 | 247 | 19 | 9 | 4 | 7 | 1 | 3 | 15 | 2
